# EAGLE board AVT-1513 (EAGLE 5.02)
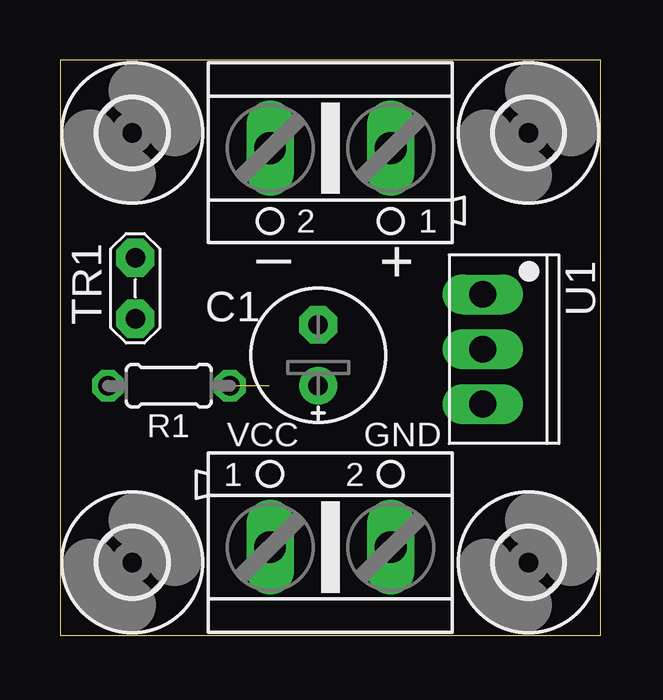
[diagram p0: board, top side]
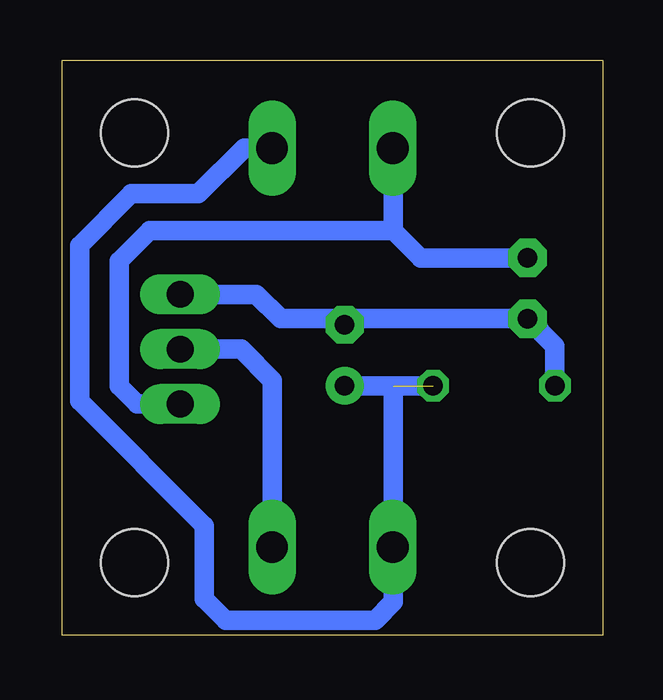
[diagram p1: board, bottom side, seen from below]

Size 22.53 x 23.99 mm. Coordinates in mm from the lower left corner, seen from the top.
Outline: 0,0 22.53,0 22.53,23.99 0,23.99 0,0
Copper layers (1*16): Top 0.035mm / dielectric 1.5mm / Bottom 0.035mm
Design rules "default": minimum track width 10mil, minimum drill 24mil, track to track 8mil, track to pad 8mil, pad to pad 8mil, via to via 8mil, smd to smd 8mil, copper to edge 40mil, drill to drill 8mil, minimum pad ring 10mil, minimum via ring 8mil, stop-mask expansion 4mil, vias tented up to drill 0mil, thermal gap 10mil

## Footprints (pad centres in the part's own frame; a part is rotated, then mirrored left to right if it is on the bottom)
E2,5-6E = drill 0.813 pad 1.575 round: + -1.27,0 | drill 0.813 pad 1.575 octagon: - 1.27,0
2,8 = hole 2.8: 0,0
0204/5 = drill 0.813 octagon: 1 -2.54,0; 2 2.54,0
RS-2,5 = drill 0.813 pad 1.6 octagon: 1 -1.27,0; 2 1.27,0
TO126 = drill 1.118 long: 1 -2.286,-2.54; 2 0,-2.54; 3 2.286,-2.54
AK500/2 = drill 1.321 long: 1 -2.515,0; 2 2.515,0

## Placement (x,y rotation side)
C1  [E2,5-6E]  10.76,11.68 90 top
H5  MOUNT-HOLE2.8  [2,8]  3.01,3.04 0 top
H6  MOUNT-HOLE2.8  [2,8]  19.52,3.04 0 top
H7  MOUNT-HOLE2.8  [2,8]  19.52,20.95 0 top
H8  MOUNT-HOLE2.8  [2,8]  3.01,20.95 0 top
R1  [0204/5]  4.53,10.41 180 top
TR1  [RS-2,5]  3.14,14.47 90 top
U1  TDA1151  [TO126]  20.15,11.93 270 top
X1  [AK500/2]  11.27,3.68 0 top
X2  [AK500/2]  11.27,20.32 180 top

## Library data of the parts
C1 R1 = rcl
H5-H8 = holes
TR1 = discrete
U1 = moja
X1 X2 = con-ptr500

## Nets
N$1: C1.- R1.2 TR1.1 U1.1
N$2: C1.+ R1.1 X1.1 X2.1
N$3: TR1.2 U1.3 X2.2
N$4: U1.2 X1.2

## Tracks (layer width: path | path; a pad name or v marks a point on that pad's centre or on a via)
N$1
  Bottom 0.813: R1.2 1.99,12.06 TR1.1 10.63,13.2 | 10.63,13.2 13.42,13.2 14.44,14.22 U1.1 | C1.- 10.76,13.08 10.63,13.2
N$2  (1 unrouted)
  Bottom 0.813: R1.1 8.73,10.41 | 8.73,10.41 C1.+ | 8.73,3.68 X1.1 | 8.73,3.68 8.73,10.41 | X2.1 14.95,20.32 16.85,18.41 19.65,18.41 21.81,16.25 21.81,9.77 16.6,4.57 16.6,1.52 15.71,0.63 9.49,0.63 8.73,1.39 8.73,3.68
N$3
  Bottom 0.813: TR1.2 7.58,15.74 8.73,16.89 | X2.2 8.73,20.32 8.73,16.89 | U1.3 19.39,9.65 20.15,10.41 20.15,15.62 18.88,16.89 8.73,16.89
N$4
  Bottom 0.813: X1.2 13.78,10.64 15.08,11.93 U1.2

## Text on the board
tNames: _ | + | VCC | GND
